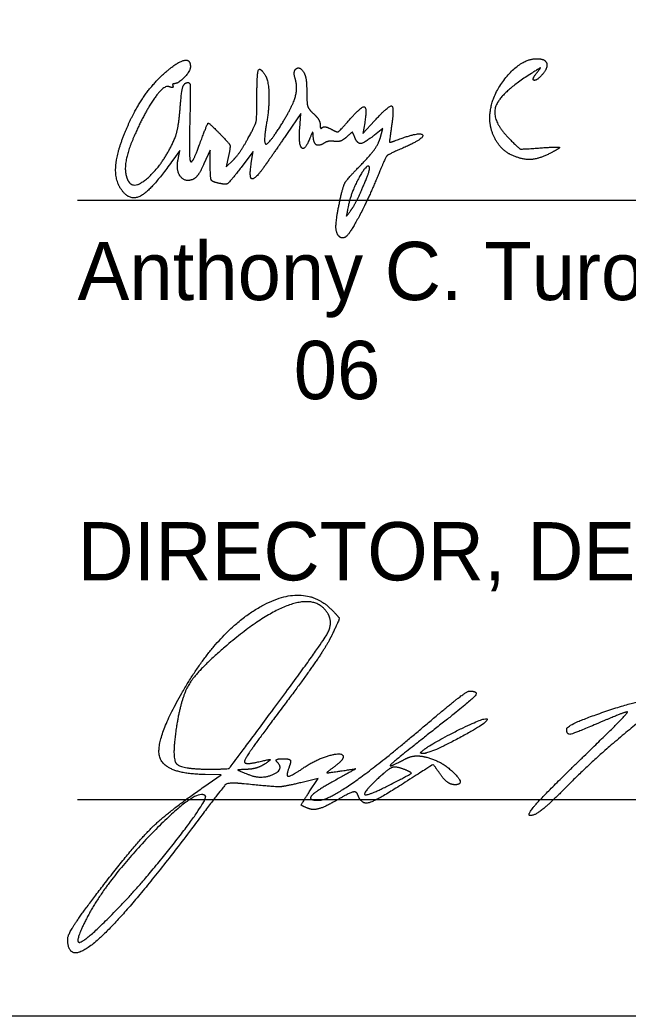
# Model space of a CAD drawing. Extents: x 0 to 34, y -6.2 to 22.
# Drawn here: x 25.966 to 27.428, y 0.5 to 2.894 of the extents above; entities that cross this region are included whole.
import ezdxf

# ---------------------------------------------------------------- set-up
doc = ezdxf.new("R2010")
doc.units = 0
for name, color, linetype in [('SH_Border', 7, 'Continuous'), ('SH_Data', 7, 'Continuous'), ('SH_Text', 7, 'Continuous')]:
    doc.layers.add(name, color=color, linetype=linetype)

msp = doc.modelspace()

# ---------------------------------------------------------------- linework, layer by layer
at = {"layer": 'SH_Border'}
msp.add_lwpolyline([(2, 21.5), (33.5, 21.5), (33.5, 0.5), (2, 0.5)], close=True, dxfattribs=at)
at = {"layer": 'SH_Data'}
for p, q in [((26.104, 2.4607), (29.604, 2.4607)), ((26.104, 1.0203), (29.604, 1.0203))]:
    msp.add_line(p, q, dxfattribs=at)
at = {"layer": 'SH_Text'}
for p, q in [((27.145, 2.5708), (27.145, 2.5708)), ((26.7916, 2.495), (26.7916, 2.495)), ((26.7331, 2.374), (26.7331, 2.374)), ((26.5662, 1.2254), (26.5662, 1.2254)), ((26.9316, 1.1355), (26.9316, 1.1355)), ((27.3034, 1.1065), (27.3034, 1.1065)), ((26.8868, 1.0939), (26.8868, 1.0939)), ((26.1958, 0.7528), (26.1958, 0.7528)), ((26.0805, 0.686), (26.0805, 0.686))]:
    msp.add_line(p, q, dxfattribs=at)
for points in [[(26.6384, 2.6334), (26.6409, 2.6688), (26.608, 2.6208)], [(26.7948, 2.6465), (26.7905, 2.6208), (26.8185, 2.6516)], [(26.8317, 2.6091), (26.8385, 2.6332), (26.818, 2.617)], [(26.3458, 2.5584), (26.35, 2.5805), (26.3331, 2.5566)], [(26.4234, 2.5437), (26.4232, 2.5808), (26.4083, 2.548)], [(26.4675, 2.5671), (26.462, 2.5408), (26.4781, 2.5568)], [(26.5221, 2.5494), (26.5268, 2.578), (26.4994, 2.5421)], [(26.4186, 1.0584), (26.4493, 1.0797), (26.4115, 1.0803)], [(26.6615, 1.0386), (26.6827, 1.0709), (26.641, 1.0609)]]:
    msp.add_lwpolyline(points, dxfattribs=at)
for points in [[(26.3197, 2.7717), (26.3466, 2.7943), (26.3756, 2.7996), (26.3756, 2.782)], [(26.3756, 2.782), (26.3756, 2.7714), (26.3467, 2.7408), (26.3367, 2.7408)], [(26.6277, 2.7525), (26.6219, 2.7708), (26.6386, 2.7832), (26.6483, 2.7678)], [(27.0957, 2.6585), (27.0962, 2.7075), (27.1706, 2.8008), (27.2093, 2.8008)], [(27.2086, 2.7667), (27.2182, 2.7788), (27.2165, 2.7786), (27.1956, 2.7654)], [(27.2093, 2.8008), (27.2282, 2.8008), (27.2363, 2.7801), (27.2235, 2.7647)], [(26.2157, 2.6171), (26.2359, 2.6684), (26.2868, 2.744), (26.3197, 2.7717)], [(26.5356, 2.7083), (26.5356, 2.7643), (26.5426, 2.7818), (26.5561, 2.7599)], [(26.5561, 2.7599), (26.5636, 2.7477), (26.5653, 2.6834), (26.559, 2.6474)], [(26.6483, 2.7678), (26.6522, 2.7618), (26.6554, 2.7403), (26.6554, 2.72)], [(27.1956, 2.7654), (27.1203, 2.7178), (27.0988, 2.6523), (27.1439, 2.6072)], [(27.2235, 2.7647), (27.2095, 2.7479), (27.1952, 2.7498), (27.2086, 2.7667)], [(26.3245, 2.7335), (26.312, 2.7384), (26.2641, 2.6701), (26.239, 2.6115)], [(26.3335, 2.7351), (26.3345, 2.7319), (26.3305, 2.7312), (26.3245, 2.7335)], [(26.3367, 2.7408), (26.3339, 2.7408), (26.3324, 2.7382), (26.3335, 2.7351)], [(26.3511, 2.6842), (26.3539, 2.7194), (26.3594, 2.7408), (26.366, 2.743)], [(26.366, 2.743), (26.3744, 2.7457), (26.376, 2.7267), (26.374, 2.6496)], [(26.5911, 2.6373), (26.6192, 2.6817), (26.6347, 2.7304), (26.6277, 2.7525)], [(26.5149, 2.6103), (26.532, 2.6414), (26.5356, 2.6583), (26.5356, 2.7083)], [(26.6554, 2.72), (26.6555, 2.6935), (26.66, 2.6792), (26.6716, 2.6688)], [(26.3379, 2.6088), (26.3426, 2.6198), (26.3486, 2.6537), (26.3511, 2.6842)], [(26.7567, 2.6524), (26.7861, 2.6864), (26.801, 2.6841), (26.7948, 2.6465)], [(26.8185, 2.6516), (26.8533, 2.6898), (26.8663, 2.6844), (26.8588, 2.6348)], [(26.6716, 2.6688), (26.6804, 2.6608), (26.6876, 2.6489), (26.6876, 2.6422)], [(27.145, 2.5708), (27.1237, 2.5811), (27.0955, 2.6313), (27.0957, 2.6585)], [(26.374, 2.6496), (26.3727, 2.5963), (26.374, 2.5528), (26.3769, 2.5528)], [(26.3962, 2.5908), (26.4162, 2.6451), (26.4202, 2.6473), (26.4482, 2.6186)], [(26.559, 2.6474), (26.5504, 2.5978), (26.5634, 2.5937), (26.5911, 2.6373)], [(26.6876, 2.6422), (26.6876, 2.6356), (26.6898, 2.6324), (26.6926, 2.6352)], [(26.6926, 2.6352), (26.6954, 2.638), (26.7051, 2.6362), (26.7143, 2.6314)], [(26.7143, 2.6314), (26.7286, 2.6237), (26.7343, 2.6265), (26.7567, 2.6524)], [(26.8588, 2.6348), (26.854, 2.6022), (26.8549, 2.5988), (26.8672, 2.6035)], [(26.2103, 2.4851), (26.1946, 2.5066), (26.1972, 2.5702), (26.2157, 2.6171)], [(26.239, 2.6115), (26.2225, 2.573), (26.2168, 2.5221), (26.2272, 2.5054)], [(26.4482, 2.6186), (26.4693, 2.597), (26.4721, 2.5895), (26.4675, 2.5671)], [(26.4781, 2.5568), (26.487, 2.5656), (26.5035, 2.5897), (26.5149, 2.6103)], [(26.608, 2.6208), (26.59, 2.5944), (26.5672, 2.5612), (26.5574, 2.5471)], [(26.6631, 2.6101), (26.6508, 2.5794), (26.6357, 2.5937), (26.6384, 2.6334)], [(26.6711, 2.6153), (26.6707, 2.6247), (26.6683, 2.6232), (26.6631, 2.6101)], [(26.6976, 2.5981), (26.6845, 2.5899), (26.6717, 2.5982), (26.6711, 2.6153)], [(26.7513, 2.6125), (26.7434, 2.6054), (26.7303, 2.6006), (26.7222, 2.602)], [(26.7703, 2.6131), (26.7661, 2.6242), (26.764, 2.6241), (26.7513, 2.6125)], [(26.818, 2.617), (26.7934, 2.5976), (26.7768, 2.5963), (26.7703, 2.6131)], [(26.8672, 2.6035), (26.9267, 2.6264), (26.941, 2.6094), (26.8832, 2.5846)], [(26.2272, 2.5054), (26.2405, 2.4839), (26.313, 2.5517), (26.3379, 2.6088)], [(26.3769, 2.5528), (26.3798, 2.5528), (26.3885, 2.5699), (26.3962, 2.5908)], [(26.7222, 2.602), (26.7142, 2.6033), (26.7031, 2.6016), (26.6976, 2.5981)], [(26.7847, 2.5444), (26.8067, 2.5668), (26.8279, 2.5959), (26.8317, 2.6091)], [(27.1439, 2.6072), (27.1666, 2.5845), (27.1713, 2.5831), (27.2159, 2.5864)], [(27.2159, 2.5864), (27.2421, 2.5883), (27.2636, 2.5888), (27.2636, 2.5875)], [(27.2636, 2.5875), (27.2636, 2.5862), (27.2529, 2.5797), (27.24, 2.573)], [(26.8832, 2.5846), (26.8517, 2.5711), (26.8444, 2.5633), (26.8296, 2.5269)], [(27.24, 2.573), (27.2127, 2.5589), (27.1717, 2.558), (27.145, 2.5708)], [(26.3331, 2.5566), (26.2834, 2.4868), (26.2313, 2.4565), (26.2103, 2.4851)], [(26.3812, 2.5105), (26.3624, 2.5033), (26.3409, 2.5324), (26.3458, 2.5584)], [(26.4083, 2.548), (26.4001, 2.53), (26.3879, 2.5131), (26.3812, 2.5105)], [(26.4376, 2.503), (26.4268, 2.5058), (26.4235, 2.5152), (26.4234, 2.5437)], [(26.4994, 2.5421), (26.4701, 2.5038), (26.4597, 2.4973), (26.4376, 2.503)], [(26.5574, 2.5471), (26.5326, 2.5113), (26.5161, 2.5124), (26.5221, 2.5494)], [(26.7361, 2.4639), (26.7428, 2.495), (26.7534, 2.5126), (26.7847, 2.5444)], [(26.8056, 2.5414), (26.799, 2.5481), (26.762, 2.4793), (26.7558, 2.4488)], [(26.7916, 2.495), (26.8016, 2.5183), (26.8079, 2.5391), (26.8056, 2.5414)], [(26.8296, 2.5269), (26.8044, 2.4652), (26.7559, 2.3743), (26.7466, 2.3711)], [(26.7618, 2.4368), (26.7683, 2.4456), (26.7817, 2.4718), (26.7916, 2.495)], [(26.7331, 2.374), (26.7251, 2.3819), (26.7263, 2.4182), (26.7361, 2.4639)], [(26.7558, 2.4488), (26.7506, 2.4228), (26.751, 2.422), (26.7618, 2.4368)], [(26.7466, 2.3711), (26.7422, 2.3697), (26.7361, 2.3709), (26.7331, 2.374)], [(26.355, 1.2762), (26.4412, 1.4265), (26.6493, 1.5426), (26.715, 1.4769)], [(26.706, 1.4677), (26.6801, 1.5097), (26.554, 1.4686), (26.4586, 1.3869)], [(26.5662, 1.2254), (26.6876, 1.3888), (26.72, 1.445), (26.706, 1.4677)], [(26.715, 1.4769), (26.7338, 1.4581), (26.7338, 1.4531), (26.7155, 1.4147)], [(26.7155, 1.4147), (26.7045, 1.3917), (26.6528, 1.3161), (26.6005, 1.2467)], [(26.4586, 1.3869), (26.392, 1.3299), (26.3531, 1.2658), (26.342, 1.1945)], [(26.4115, 1.0803), (26.3135, 1.082), (26.2901, 1.1631), (26.355, 1.2762)], [(26.9451, 1.2027), (26.9955, 1.2455), (27.041, 1.2807), (27.0462, 1.2808)], [(27.0462, 1.2808), (27.071, 1.2813), (27.0477, 1.2557), (26.9618, 1.1885)], [(27.5778, 1.2879), (27.5682, 1.2975), (27.3584, 1.1306), (27.2805, 1.0513)], [(26.6005, 1.2467), (26.5483, 1.1774), (26.5055, 1.1167), (26.5055, 1.1119)], [(27.2807, 1.1903), (27.281, 1.2009), (27.4683, 1.2641), (27.4841, 1.2589)], [(26.4201, 1.0935), (26.4668, 1.0935), (26.4714, 1.0976), (26.5662, 1.2254)], [(27.3034, 1.1065), (27.3744, 1.175), (27.4297, 1.231), (27.4263, 1.231)], [(27.4263, 1.231), (27.4229, 1.231), (27.3939, 1.2197), (27.3618, 1.206)], [(26.6837, 1.0185), (26.7068, 1.0185), (26.8328, 1.1073), (26.9451, 1.2027)], [(26.9316, 1.1355), (26.952, 1.1534), (27.084, 1.2192), (27.0892, 1.214)], [(27.0892, 1.214), (27.0954, 1.2078), (26.9527, 1.131), (26.9351, 1.131)], [(27.3618, 1.206), (27.2992, 1.1791), (27.2804, 1.1755), (27.2807, 1.1903)], [(26.342, 1.1945), (26.3306, 1.1212), (26.352, 1.0935), (26.4201, 1.0935)], [(26.9618, 1.1885), (26.8686, 1.1154), (26.8471, 1.0939), (26.891, 1.1174)], [(26.6496, 1.0978), (26.6785, 1.1176), (26.743, 1.1351), (26.743, 1.1232)], [(26.891, 1.1174), (26.9037, 1.1241), (26.9276, 1.1262), (26.9442, 1.122)], [(26.9351, 1.131), (26.9303, 1.131), (26.9287, 1.133), (26.9316, 1.1355)], [(26.5055, 1.1119), (26.5055, 1.1072), (26.521, 1.1068), (26.5399, 1.1112)], [(26.5555, 1.1065), (26.5452, 1.0996), (26.5255, 1.0934), (26.5118, 1.0929)], [(26.516, 1.0802), (26.5458, 1.0682), (26.6021, 1.0928), (26.5846, 1.1102)], [(26.5399, 1.1112), (26.5654, 1.1172), (26.5695, 1.1159), (26.5555, 1.1065)], [(26.5846, 1.1102), (26.5801, 1.1147), (26.5864, 1.1185), (26.5986, 1.1185)], [(26.5986, 1.1185), (26.6131, 1.1185), (26.6183, 1.112), (26.6135, 1.0997)], [(26.743, 1.1232), (26.743, 1.1187), (26.7333, 1.1079), (26.7214, 1.0991)], [(26.9772, 1.0806), (26.9603, 1.1047), (26.9583, 1.1043), (26.8925, 1.0619)], [(26.9442, 1.122), (26.9802, 1.1129), (27.0386, 1.056), (27.0119, 1.056)], [(27.193, 0.9817), (27.1827, 0.9819), (27.2324, 1.038), (27.3034, 1.1065)], [(26.5118, 1.0929), (26.4894, 1.092), (26.4898, 1.0907), (26.516, 1.0802)], [(26.6135, 1.0997), (26.6046, 1.0765), (26.6174, 1.0758), (26.6496, 1.0978)], [(26.7214, 1.0991), (26.7025, 1.0853), (26.7045, 1.084), (26.737, 1.089)], [(26.737, 1.089), (26.7738, 1.0945), (26.7737, 1.0943), (26.7282, 1.0691)], [(26.8337, 1.0773), (26.7894, 1.0369), (26.8007, 1.028), (26.8587, 1.0576)], [(26.8868, 1.0939), (26.8696, 1.1002), (26.8531, 1.0951), (26.8337, 1.0773)], [(26.8587, 1.0576), (26.905, 1.0812), (26.9086, 1.0858), (26.8868, 1.0939)], [(27.0119, 1.056), (27.0023, 1.056), (26.9867, 1.0671), (26.9772, 1.0806)], [(26.1677, 0.8163), (26.2453, 0.9167), (26.3254, 0.994), (26.4186, 1.0584)], [(26.4998, 1.0585), (26.4664, 1.0619), (26.4547, 1.0514), (26.378, 0.9497)], [(26.641, 1.0609), (26.6007, 1.0511), (26.5783, 1.0507), (26.4998, 1.0585)], [(26.7282, 1.0691), (26.6772, 1.0409), (26.6574, 1.0185), (26.6837, 1.0185)], [(26.8925, 1.0619), (26.8237, 1.0175), (26.7862, 1.0078), (26.7781, 1.0322)], [(26.4115, 1.0292), (26.3906, 1.0501), (26.1721, 0.8244), (26.1257, 0.7341)], [(26.6603, 0.9985), (26.6422, 1.0055), (26.6423, 1.0092), (26.6615, 1.0386)], [(26.7781, 1.0322), (26.7752, 1.0407), (26.756, 1.0355), (26.7269, 1.0184)], [(27.2805, 1.0513), (27.2427, 1.0128), (27.2034, 0.9815), (27.193, 0.9817)], [(26.1958, 0.7528), (26.2634, 0.8219), (26.4192, 1.0215), (26.4115, 1.0292)], [(26.7269, 1.0184), (26.7013, 1.0032), (26.6713, 0.9943), (26.6603, 0.9985)], [(26.378, 0.9497), (26.2256, 0.7476), (26.0805, 0.619), (26.0805, 0.686)], [(26.0805, 0.686), (26.0805, 0.6956), (26.1198, 0.7542), (26.1677, 0.8163)], [(26.1257, 0.7341), (26.0945, 0.6731), (26.1261, 0.6816), (26.1958, 0.7528)]]:
    msp.add_open_spline(points, degree=2, dxfattribs=at)

# ---------------------------------------------------------------- texts
for s, p in [('Anthony C. Turowski, P.E.', (26.104, 2.2207)), ('          06', (26.104, 1.9827)), ('DIRECTOR, DEPARTMENT OF TRANSPORTATION', (26.104, 1.5471))]:
    msp.add_text(s, height=0.14, dxfattribs=at).set_placement(p)

doc.saveas('drawing.dxf')
